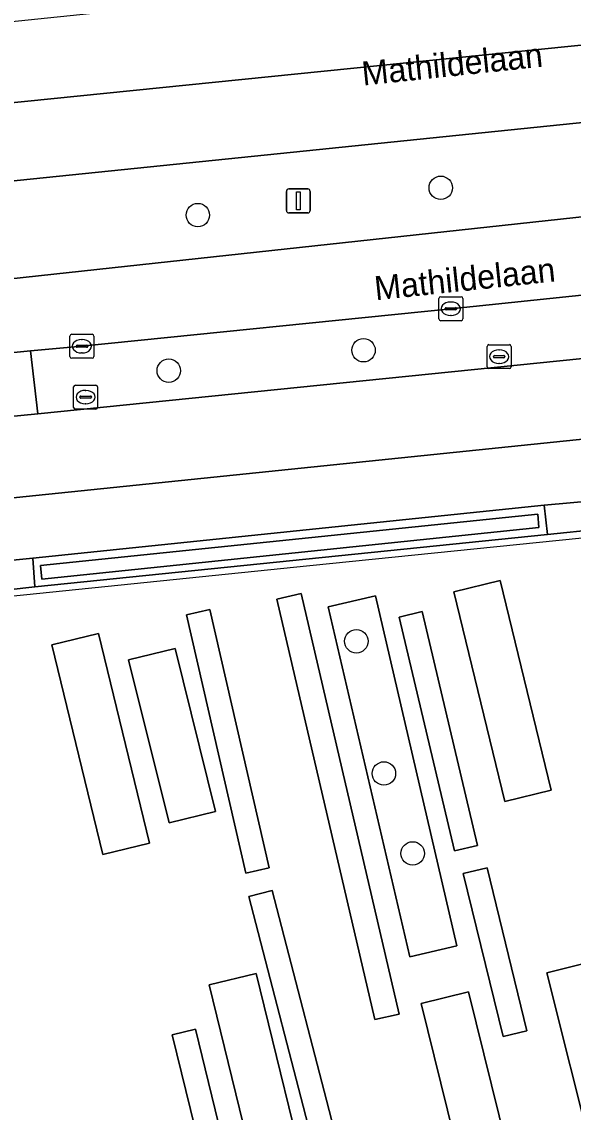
# Model space of a CAD drawing. Extents: x 160675 to 161153, y 383241 to 383714.
# Drawn here: x 161053 to 161076.02, y 383524.51 to 383570.01 of the extents above; entities that cross this region are included whole.
import ezdxf

# ---------------------------------------------------------------- set-up
doc = ezdxf.new("R2010")
doc.units = 0
for name, color, linetype in [('IMGEO_Berm_groen', 7, 'Continuous'), ('IMGEO_Boom', 7, 'Continuous'), ('IMGEO_Erf', 7, 'Continuous'), ('IMGEO_Fietspad_gesloten', 7, 'Continuous'), ('IMGEO_Grasland_overig', 7, 'Continuous'), ('IMGEO_Kolk', 7, 'Continuous'), ('IMGEO_Lichtmast', 7, 'Continuous'), ('IMGEO_Lijnafwatering', 7, 'Continuous'), ('IMGEO_Muur', 7, 'Continuous'), ('IMGEO_Openbare_ruimte_label', 7, 'Continuous'), ('IMGEO_OVBaan_gesloten', 7, 'Continuous'), ('IMGEO_Rijbaan_lokaal_gesloten', 7, 'Continuous'), ('IMGEO_Rijbaan_lokaal_open', 7, 'Continuous'), ('IMGEO_Voetpad_open', 7, 'Continuous')]:
    doc.layers.add(name, color=color, linetype=linetype)

msp = doc.modelspace()

# ---------------------------------------------------------------- linework, layer by layer
at = {"layer": 'IMGEO_Berm_groen'}
for points in [[(161128.627, 383571.185), (161015.36, 383559.547)], [(161015.911, 383554.341), (161040.346, 383557.963), (161129.447, 383567.638)]]:
    msp.add_lwpolyline(points, dxfattribs=at)
msp.add_lwpolyline([(161130.013, 383561.398), (161129.727, 383564.069), (161127.623, 383563.879), (161106.689, 383561.735), (161089.308, 383559.955), (161070.913, 383558.041), (161055.51, 383556.475), (161053.368, 383556.276), (161053.666, 383553.653)], close=True, dxfattribs=at)
at = {"layer": 'IMGEO_Boom'}
for centre in [(161070.49, 383563.086), (161060.349, 383561.947), (161067.266, 383556.306), (161059.135, 383555.455), (161066.967, 383544.162), (161068.117, 383538.646), (161069.316, 383535.31)]:
    msp.add_circle(centre, 0.489, dxfattribs=at)
at = {"layer": 'IMGEO_Erf'}
msp.add_lwpolyline([(161120.104, 383550.651), (161119.769, 383552.41), (161119.664, 383552.859), (161119.596, 383553.151), (161105.929, 383551.792), (161103.728, 383551.582), (161077.097, 383548.842), (161074.948, 383548.624), (161053.543, 383546.435), (161048.833, 383545.9)], dxfattribs=at)
for points in [[(161073.163, 383537.475), (161071.039, 383546.228), (161072.974, 383546.698), (161075.098, 383537.944)], [(161068.748, 383528.608), (161067.738, 383528.372), (161063.649, 383545.917), (161064.659, 383546.152)], [(161069.199, 383530.992), (161065.793, 383545.605), (161067.761, 383546.064), (161071.167, 383531.451)], [(161062.358, 383534.488), (161059.872, 383545.264), (161060.847, 383545.489), (161063.333, 383534.713)], [(161071.066, 383535.418), (161068.754, 383545.173), (161069.715, 383545.401), (161072.027, 383535.645)], [(161058.331, 383535.735), (161056.384, 383535.26), (161054.249, 383544.013), (161056.196, 383544.488)], [(161061.086, 383537.061), (161059.147, 383536.58), (161057.459, 383543.386), (161059.397, 383543.867)], [(161074.087, 383527.911), (161073.098, 383527.669), (161071.432, 383534.471), (161072.422, 383534.714)], [(161065.248, 383522.826), (161062.478, 383533.507), (161063.45, 383533.759), (161066.219, 383523.078)], [(161076.883, 383522.511), (161074.916, 383530.322), (161076.86, 383530.811), (161078.827, 383523.001)], [(161065.168, 383520.586), (161063.202, 383520.103), (161060.818, 383529.82), (161062.785, 383530.302)], [(161073.573, 383521.766), (161071.594, 383521.276), (161069.672, 383529.042), (161071.651, 383529.532)], [(161061.196, 383519.927), (161059.283, 383527.732), (161060.25, 383527.969), (161062.162, 383520.164)]]:
    msp.add_lwpolyline(points, close=True, dxfattribs=at)
at = {"layer": 'IMGEO_Fietspad_gesloten'}
for points in [[(161127.202, 383557.831), (161129.695, 383558.017), (161132.245, 383558.207), (161131.905, 383560.511), (161131.751, 383561.552), (161130.013, 383561.398), (161053.666, 383553.653), (161047.67, 383553.068), (161040.812, 383552.349)], [(161030.95, 383547.693), (161037.578, 383548.506), (161047.631, 383549.64), (161127.202, 383557.831)]]:
    msp.add_lwpolyline(points, dxfattribs=at)
at = {"layer": 'IMGEO_Grasland_overig'}
for points in [[(161074.591, 383548.907), (161074.537, 383549.468), (161053.787, 383547.325), (161053.843, 383546.754)], [(161075.098, 383537.944), (161072.974, 383546.698), (161071.039, 383546.228), (161073.163, 383537.475)], [(161064.659, 383546.152), (161063.649, 383545.917), (161067.738, 383528.372), (161068.748, 383528.608)], [(161071.167, 383531.451), (161067.761, 383546.064), (161065.793, 383545.605), (161069.199, 383530.992)], [(161063.333, 383534.713), (161060.847, 383545.489), (161059.872, 383545.264), (161062.358, 383534.488)], [(161072.027, 383535.645), (161069.715, 383545.401), (161068.754, 383545.173), (161071.066, 383535.418)], [(161056.196, 383544.488), (161054.249, 383544.013), (161056.384, 383535.26), (161058.331, 383535.735)], [(161059.397, 383543.867), (161057.459, 383543.386), (161059.147, 383536.58), (161061.086, 383537.061)], [(161072.422, 383534.714), (161071.432, 383534.471), (161073.098, 383527.669), (161074.087, 383527.911)], [(161066.219, 383523.078), (161063.45, 383533.759), (161062.478, 383533.507), (161065.248, 383522.826)], [(161078.827, 383523.001), (161076.86, 383530.811), (161074.916, 383530.322), (161076.883, 383522.511)], [(161062.785, 383530.302), (161060.818, 383529.82), (161063.202, 383520.103), (161065.168, 383520.586)], [(161071.651, 383529.532), (161069.672, 383529.042), (161071.594, 383521.276), (161073.573, 383521.766)], [(161062.162, 383520.164), (161060.25, 383527.969), (161059.283, 383527.732), (161061.196, 383519.927)]]:
    msp.add_lwpolyline(points, close=True, dxfattribs=at)
at = {"layer": 'IMGEO_Kolk'}
for p, q in [((161070.487, 383558.541), (161071.339, 383558.541)), ((161070.412, 383557.615), (161070.412, 383558.467)), ((161070.714, 383558.084), (161071.112, 383558.084)), ((161070.9, 383558.321), (161070.925, 383558.321)), ((161071.413, 383558.467), (161071.413, 383557.615)), ((161070.671, 383558.035), (161070.671, 383558.047)), ((161071.109, 383557.998), (161070.711, 383557.998)), ((161070.923, 383557.761), (161070.898, 383557.761)), ((161071.155, 383558.047), (161071.155, 383558.035)), ((161071.339, 383557.541), (161070.487, 383557.541)), ((161055.009, 383556.049), (161055.009, 383556.901)), ((161055.084, 383556.975), (161055.936, 383556.975)), ((161055.497, 383556.755), (161055.522, 383556.755)), ((161056.01, 383556.901), (161056.01, 383556.049)), ((161055.268, 383556.469), (161055.268, 383556.481)), ((161055.706, 383556.432), (161055.308, 383556.432)), ((161055.311, 383556.518), (161055.709, 383556.518)), ((161055.752, 383556.481), (161055.752, 383556.469)), ((161072.426, 383555.614), (161072.426, 383556.466)), ((161072.501, 383556.54), (161073.353, 383556.54)), ((161072.914, 383556.32), (161072.939, 383556.32)), ((161073.427, 383556.466), (161073.427, 383555.614)), ((161055.936, 383555.975), (161055.084, 383555.975)), ((161055.52, 383556.195), (161055.495, 383556.195)), ((161072.685, 383556.034), (161072.685, 383556.046)), ((161073.123, 383555.997), (161072.725, 383555.997)), ((161072.728, 383556.083), (161073.126, 383556.083)), ((161073.169, 383556.046), (161073.169, 383556.034)), ((161073.353, 383555.54), (161072.501, 383555.54)), ((161072.937, 383555.76), (161072.912, 383555.76)), ((161055.164, 383553.925), (161055.164, 383554.777)), ((161055.239, 383554.851), (161056.091, 383554.851)), ((161055.652, 383554.631), (161055.677, 383554.631)), ((161056.165, 383554.777), (161056.165, 383553.925)), ((161055.423, 383554.345), (161055.423, 383554.357)), ((161055.861, 383554.308), (161055.463, 383554.308)), ((161055.466, 383554.394), (161055.864, 383554.394)), ((161055.675, 383554.071), (161055.65, 383554.071)), ((161055.907, 383554.357), (161055.907, 383554.345)), ((161056.091, 383553.851), (161055.239, 383553.851))]:
    msp.add_line(p, q, dxfattribs=at)
for points in [[(161070.487, 383558.541), (161071.339, 383558.541)], [(161070.412, 383557.615), (161070.412, 383558.467)], [(161071.413, 383558.467), (161071.413, 383557.615)], [(161071.339, 383557.541), (161070.487, 383557.541)], [(161055.009, 383556.049), (161055.009, 383556.901)], [(161055.084, 383556.975), (161055.936, 383556.975)], [(161056.01, 383556.901), (161056.01, 383556.049)], [(161072.426, 383555.614), (161072.426, 383556.466)], [(161072.501, 383556.54), (161073.353, 383556.54)], [(161073.427, 383556.466), (161073.427, 383555.614)], [(161055.936, 383555.975), (161055.084, 383555.975)], [(161073.353, 383555.54), (161072.501, 383555.54)], [(161055.164, 383553.925), (161055.164, 383554.777)], [(161055.239, 383554.851), (161056.091, 383554.851)], [(161056.165, 383554.777), (161056.165, 383553.925)], [(161056.091, 383553.851), (161055.239, 383553.851)]]:
    msp.add_lwpolyline(points, dxfattribs=at)
for centre, radius, start, end in [((161070.489, 383558.465), 0.0765, 91.552, 178.448), ((161070.489, 383558.465), 0.0765, 91.552, 178.448), ((161071.337, 383558.465), 0.0765, 1.552, 88.448), ((161071.337, 383558.465), 0.0765, 1.552, 88.448), ((161070.711, 383558.044), 0.0403, 85.8775, 175.7526), ((161071.116, 383558.046), 0.0386, 1.7309, 96.639), ((161070.489, 383557.617), 0.0765, 181.552, 268.448), ((161070.489, 383557.617), 0.0765, 181.552, 268.448), ((161070.708, 383558.034), 0.0366, 178.938, 274.7102), ((161071.112, 383558.041), 0.043, 264.8664, 352.4533), ((161071.337, 383557.617), 0.0765, 271.552, 358.448), ((161071.337, 383557.617), 0.0765, 271.552, 358.448), ((161055.086, 383556.899), 0.0765, 91.552, 178.448), ((161055.086, 383556.899), 0.0765, 91.552, 178.448), ((161055.934, 383556.899), 0.0765, 1.552, 88.448), ((161055.934, 383556.899), 0.0765, 1.552, 88.448), ((161055.308, 383556.478), 0.0403, 85.8775, 175.7526), ((161055.305, 383556.468), 0.0366, 178.938, 274.7102), ((161055.709, 383556.475), 0.043, 264.8664, 352.4533), ((161055.713, 383556.48), 0.0386, 1.7309, 96.639), ((161072.503, 383556.464), 0.0765, 91.552, 178.448), ((161072.503, 383556.464), 0.0765, 91.552, 178.448), ((161073.351, 383556.464), 0.0765, 1.552, 88.448), ((161073.351, 383556.464), 0.0765, 1.552, 88.448), ((161055.086, 383556.051), 0.0765, 181.552, 268.448), ((161055.086, 383556.051), 0.0765, 181.552, 268.448), ((161055.934, 383556.051), 0.0765, 271.552, 358.448), ((161055.934, 383556.051), 0.0765, 271.552, 358.448), ((161072.725, 383556.043), 0.0403, 85.8775, 175.7526), ((161072.722, 383556.033), 0.0366, 178.938, 274.7102), ((161073.126, 383556.04), 0.043, 264.8664, 352.4533), ((161073.13, 383556.045), 0.0386, 1.7309, 96.639), ((161072.503, 383555.616), 0.0765, 181.552, 268.448), ((161072.503, 383555.616), 0.0765, 181.552, 268.448), ((161073.351, 383555.616), 0.0765, 271.552, 358.448), ((161073.351, 383555.616), 0.0765, 271.552, 358.448), ((161055.241, 383554.775), 0.0765, 91.552, 178.448), ((161055.241, 383554.775), 0.0765, 91.552, 178.448), ((161056.089, 383554.775), 0.0765, 1.552, 88.448), ((161056.089, 383554.775), 0.0765, 1.552, 88.448), ((161055.463, 383554.354), 0.0403, 85.8775, 175.7526), ((161055.46, 383554.344), 0.0366, 178.938, 274.7102), ((161055.864, 383554.351), 0.043, 264.8664, 352.4533), ((161055.868, 383554.356), 0.0386, 1.7309, 96.639), ((161055.241, 383553.927), 0.0765, 181.552, 268.448), ((161055.241, 383553.927), 0.0765, 181.552, 268.448), ((161056.089, 383553.927), 0.0765, 271.552, 358.448), ((161056.089, 383553.927), 0.0765, 271.552, 358.448)]:
    msp.add_arc(centre, radius, start, end, dxfattribs=at)
for centre, major_axis, ratio, start_param, end_param in [((161070.899, 383558.041), (-0.387, 0.002), 0.722429, 4.712389, 7.853982), ((161070.924, 383558.041), (-0.39, 0.002), 0.717154, 1.570796, 4.712389), ((161055.496, 383556.475), (-0.387, 0.002), 0.722429, 4.712389, 7.853982), ((161055.521, 383556.475), (-0.39, 0.002), 0.717154, 1.570796, 4.712389), ((161072.913, 383556.04), (-0.387, 0.002), 0.722429, 4.712389, 7.853982), ((161072.938, 383556.04), (-0.39, 0.002), 0.717154, 1.570796, 4.712389), ((161055.651, 383554.351), (-0.387, 0.002), 0.722429, 4.712389, 7.853982), ((161055.676, 383554.351), (-0.39, 0.002), 0.717154, 1.570796, 4.712389)]:
    msp.add_ellipse(centre, major_axis=major_axis, ratio=ratio, start_param=start_param, end_param=end_param, dxfattribs=at)
at = {"layer": 'IMGEO_Lichtmast'}
for p, q in [((161064.049, 383562.138), (161064.049, 383562.938)), ((161064.049, 383562.938), (161064.049, 383562.138)), ((161064.149, 383563.038), (161064.939, 383563.038)), ((161064.939, 383563.038), (161064.149, 383563.038)), ((161065.039, 383562.938), (161065.039, 383562.138)), ((161065.039, 383562.138), (161065.039, 383562.938)), ((161064.939, 383562.038), (161064.149, 383562.038)), ((161064.149, 383562.038), (161064.939, 383562.038))]:
    msp.add_line(p, q, dxfattribs=at)
msp.add_lwpolyline([(161064.469, 383562.913), (161064.619, 383562.913), (161064.619, 383562.163), (161064.469, 383562.163), (161064.469, 383562.913)], dxfattribs=at)
for centre, start, end in [((161064.149, 383562.938), 90, 180), ((161064.149, 383562.938), 90, 180), ((161064.939, 383562.938), 0, 90), ((161064.939, 383562.938), 360, 90), ((161064.149, 383562.138), 180, 270), ((161064.149, 383562.138), 180, 270), ((161064.939, 383562.138), 270, 0), ((161064.939, 383562.138), 270, 0)]:
    msp.add_arc(centre, 0.1, start, end, dxfattribs=at)
at = {"layer": 'IMGEO_Lijnafwatering'}
for points in [[(161083.234, 383549.156), (161065.019, 383547.304)], [(161065.019, 383547.304), (161046.804, 383545.453)]]:
    msp.add_lwpolyline(points, dxfattribs=at)
at = {"layer": 'IMGEO_Muur'}
for points in [[(161074.948, 383548.624), (161074.808, 383549.844), (161053.458, 383547.631), (161053.543, 383546.435)], [(161053.843, 383546.754), (161053.787, 383547.325), (161074.537, 383549.468), (161074.591, 383548.907)]]:
    msp.add_lwpolyline(points, close=True, dxfattribs=at)
at = {"layer": 'IMGEO_OVBaan_gesloten'}
msp.add_lwpolyline([(161099.72, 383571.421), (161128.738, 383574.467), (161128.396, 383577.816), (161127.033, 383577.671), (161125.413, 383577.499), (161107.04, 383575.646), (161088.192, 383573.701), (161084.138, 383573.282), (161038.417, 383568.551), (161015.019, 383566.144), (161015.035, 383565.999), (161015.167, 383562.758), (161045.124, 383565.881)], close=True, dxfattribs=at)
msp.add_lwpolyline([(161129.136, 383570.809), (161128.738, 383574.467), (161099.72, 383571.421), (161045.124, 383565.881), (161015.167, 383562.758), (161015.36, 383559.547), (161128.627, 383571.185)], dxfattribs=at)
at = {"layer": 'IMGEO_Rijbaan_lokaal_gesloten'}
for points in [[(161129.727, 383564.069), (161129.854, 383564.086), (161129.447, 383567.638), (161040.346, 383557.963), (161015.911, 383554.341), (161016.114, 383551.079)], [(161020.774, 383552.039), (161037.11, 383554.474), (161041.284, 383555.065), (161047.377, 383555.685), (161053.368, 383556.276), (161055.51, 383556.475), (161070.913, 383558.041), (161089.308, 383559.955), (161106.689, 383561.735), (161127.623, 383563.879), (161129.727, 383564.069)]]:
    msp.add_lwpolyline(points, dxfattribs=at)
at = {"layer": 'IMGEO_Rijbaan_lokaal_open'}
msp.add_lwpolyline([(161053.458, 383547.631), (161048.725, 383547.156), (161048.833, 383545.9), (161053.543, 383546.435)], close=True, dxfattribs=at)
at = {"layer": 'IMGEO_Voetpad_open'}
for points in [[(161120.56, 383554.468), (161127.504, 383555.214), (161127.202, 383557.831), (161047.631, 383549.64), (161037.578, 383548.506), (161030.95, 383547.693)], [(161004.97, 383541.712), (161003.856, 383538.104), (161004.192, 383538.181), (161006.871, 383538.796), (161007.673, 383538.987), (161037.703, 383546.15), (161037.74, 383545.993), (161048.725, 383547.156), (161053.458, 383547.631), (161074.808, 383549.844), (161076.976, 383550.039), (161103.63, 383552.751), (161105.809, 383552.976), (161120.56, 383554.468)]]:
    msp.add_lwpolyline(points, dxfattribs=at)
for points in [[(161053.368, 383556.276), (161047.377, 383555.685), (161047.67, 383553.068), (161053.666, 383553.653)], [(161077.097, 383548.842), (161076.976, 383550.039), (161074.808, 383549.844), (161074.948, 383548.624)]]:
    msp.add_lwpolyline(points, close=True, dxfattribs=at)

# ---------------------------------------------------------------- texts
at = {"layer": 'IMGEO_Openbare_ruimte_label'}
for p in [(161067.246, 383567.35), (161067.772, 383558.391)]:
    msp.add_text('Mathildelaan', height=1, rotation=6.024, dxfattribs=at).set_placement(p)

doc.saveas('drawing.dxf')
